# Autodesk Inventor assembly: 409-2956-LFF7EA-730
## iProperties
Created: 2010-06
Part Number: 409-2956-LFF7EA-730
Document SubType Name: Weldment
Designer: S. Boerckel
Mass: 6022.45 g
Surface Area: 2403.46 cm^2
Volume: 763.036 cm^3
Density: 7.89275 g/cm^3
Description: RH - PUMP DISCHARGE SPOOL
Weld Material: Welded Steel Mild
User Status: WELD
Material: WELDMENT
SMR: =<MATERIAL>
Author: S. Boerckel
Revision Number: B
Subject: DEMIN WATER FORWARDING PUMP SKID-7EA
